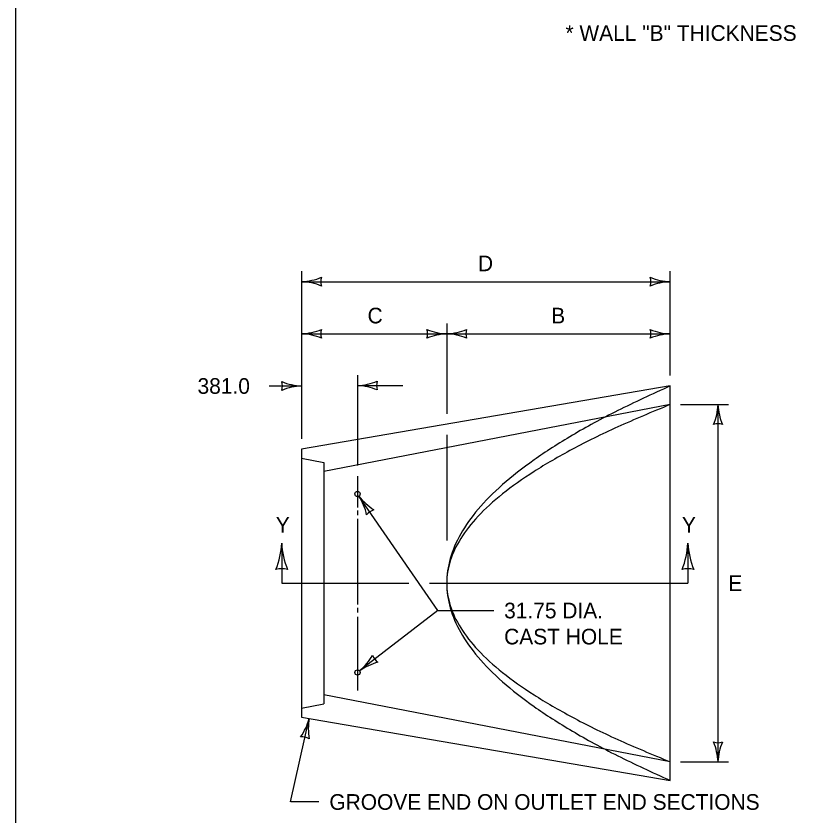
# Model space of a CAD drawing. Extents: x 49991.4 to 50022.1, y 49985 to 50011.4.
# Drawn here: x 49999.384 to 50002.424, y 49989.878 to 49992.942 of the extents above; entities that cross this region are included whole.
import ezdxf

# ---------------------------------------------------------------- set-up
doc = ezdxf.new("R2010")
doc.units = 0
for name, color, linetype in [('Level 1', 7, 'Continuous'), ('Level 2', 7, 'Continuous'), ('Level 3', 7, 'Continuous'), ('Level 4', 7, 'Continuous'), ('Level 5', 7, 'Continuous'), ('Level 6', 7, 'Continuous')]:
    doc.layers.add(name, color=color, linetype=linetype)

msp = doc.modelspace()

# ---------------------------------------------------------------- linework, layer by layer
at = {"layer": 'Level 1'}
for p, q in [((50001.8913, 49991.5236), (50000.4787, 49991.281)), ((50001.8913, 49990.011), (50001.8913, 49991.5236)), ((50000.4787, 49991.281), (50000.4787, 49990.2536)), ((50000.4787, 49990.2536), (50001.8913, 49990.011))]:
    msp.add_line(p, q, dxfattribs=at)
msp.add_lwpolyline([(49999.3835, 49998.9992), (50016.7501, 49998.9992), (50016.7501, 49987.7988), (49999.3835, 49987.7988)], close=True, dxfattribs=at)
for centre in [(50000.6927, 49991.1097), (50000.6927, 49990.4248)]:
    msp.add_circle(centre, 0.0102, dxfattribs=at)
for points in [[(50001.8913, 49991.5236), (50000.179, 49990.7673), (50001.8913, 49990.011)], [(50001.8913, 49991.4522), (50000.179, 49990.7673), (50001.8913, 49990.0823)]]:
    msp.add_open_spline(points, degree=2, dxfattribs=at)
at = {"layer": 'Level 3'}
for p, q in [((50000.4787, 49991.9636), (50000.4787, 49991.321)), ((50001.8913, 49991.5636), (50001.8913, 49991.9636)), ((50000.4787, 49991.9236), (50001.8913, 49991.9236)), ((50001.0352, 49991.7636), (50001.0352, 49991.4166)), ((50000.4787, 49991.7236), (50001.0352, 49991.7236)), ((50001.0352, 49991.7236), (50001.8913, 49991.7236)), ((50000.6927, 49991.5652), (50000.6927, 49991.3207)), ((50000.3537, 49991.5236), (50000.4787, 49991.5236)), ((50000.6927, 49991.5252), (50000.8661, 49991.5252)), ((50001.9313, 49991.4522), (50002.115, 49991.4522)), ((50002.075, 49991.4522), (50002.075, 49990.0823)), ((50001.0352, 49991.3366), (50001.0352, 49991.258)), ((50000.6927, 49991.3207), (50000.6927, 49991.2182)), ((50001.0352, 49991.258), (50001.0352, 49990.9309)), ((50001.0014, 49990.6625), (50000.6985, 49991.1013)), ((50001.0014, 49990.6625), (50000.7008, 49990.431)), ((50001.0014, 49990.6625), (50001.2151, 49990.6625)), ((50000.4364, 49989.9283), (50000.5077, 49990.2486)), ((50001.9313, 49990.0823), (50002.115, 49990.0823)), ((50000.545, 49989.9283), (50000.4377, 49989.9283))]:
    msp.add_line(p, q, dxfattribs=at)
for centre, radius, start, end in [((50000.4672, 49992.1563), 0.233, 272.8273, 292.0772), ((50000.4695, 49991.7015), 0.2223, 67.456, 87.6395), ((50000.6069, 49991.9236), 0.0548, 162.1388, 197.8612), ((50001.9005, 49992.1457), 0.2223, 247.456, 267.6395), ((50001.7631, 49991.9236), 0.0548, 342.1388, 17.8612), ((50001.9028, 49991.6909), 0.233, 92.8273, 112.0772), ((50000.4672, 49991.9563), 0.233, 272.8273, 292.0772), ((50000.6069, 49991.7236), 0.0548, 162.1388, 197.8612), ((50001.0444, 49991.9457), 0.2223, 247.456, 267.6395), ((50000.907, 49991.7236), 0.0548, 342.1388, 17.8612), ((50001.0237, 49991.9563), 0.233, 272.8273, 292.0772), ((50001.1634, 49991.7236), 0.0548, 162.1388, 197.8612), ((50001.9005, 49991.9457), 0.2223, 247.456, 267.6395), ((50001.7631, 49991.7236), 0.0548, 342.1388, 17.8612), ((50000.4695, 49991.5015), 0.2223, 67.456, 87.6395), ((50001.0467, 49991.4909), 0.233, 92.8273, 112.0772), ((50001.026, 49991.5015), 0.2223, 67.456, 87.6395), ((50001.9028, 49991.4909), 0.233, 92.8273, 112.0772), ((50000.4879, 49991.7457), 0.2223, 247.456, 267.6395), ((50000.3505, 49991.5236), 0.0548, 342.1388, 17.8612), ((50000.4902, 49991.2909), 0.233, 92.8273, 112.0772), ((50000.6812, 49991.7579), 0.233, 272.8273, 292.0772), ((50000.6835, 49991.3031), 0.2223, 67.456, 87.6395), ((50000.8209, 49991.5252), 0.0548, 162.1388, 197.8612), ((50001.8529, 49991.4614), 0.2223, 337.456, 357.6395), ((50002.3077, 49991.4637), 0.233, 182.8273, 202.0772), ((50002.075, 49991.324), 0.0548, 72.1388, 107.8612), ((50000.5105, 49990.9827), 0.2223, 12.073, 32.2565), ((50000.8835, 49991.243), 0.233, 217.4443, 236.6942), ((50000.7713, 49990.9958), 0.0548, 106.7558, 142.4782), ((50000.1061, 49990.9332), 0.2964, 337.456, 357.6395), ((50000.7126, 49990.9363), 0.3107, 182.8273, 202.0772), ((50001.6633, 49990.9332), 0.2964, 337.456, 357.6395), ((50002.2698, 49990.9363), 0.3107, 182.8273, 202.0772), ((50000.4023, 49990.75), 0.073, 72.1388, 107.8612), ((50001.9595, 49990.75), 0.073, 72.1388, 107.8612), ((50000.5497, 49990.6084), 0.233, 310.4281, 329.678), ((50000.8024, 49990.5092), 0.0548, 199.7396, 235.462), ((50000.8291, 49990.2494), 0.2223, 105.0568, 125.2403), ((50000.2928, 49990.3058), 0.2223, 324.9059, 345.0894), ((50000.7373, 49990.2093), 0.233, 170.2772, 189.5271), ((50000.4798, 49990.1235), 0.0548, 59.5887, 95.3111), ((50002.075, 49990.2105), 0.0548, 252.1388, 287.8612), ((50001.8423, 49990.0708), 0.233, 2.8273, 22.0772), ((50002.2971, 49990.0731), 0.2223, 157.456, 177.6395)]:
    msp.add_arc(centre, radius, start, end, dxfattribs=at)
at = {"layer": 'Level 4'}
for p, q in [((50001.8913, 49991.4522), (50000.5642, 49991.1953)), ((50000.4787, 49991.2467), (50000.5642, 49991.2296)), ((50000.5642, 49991.2296), (50000.5642, 49990.305)), ((50001.8913, 49990.0823), (50000.5642, 49990.3392)), ((50000.4787, 49990.2878), (50000.5642, 49990.305))]:
    msp.add_line(p, q, dxfattribs=at)
at = {"layer": 'Level 5'}
for p, q in [((50000.6927, 49991.1782), (50000.6927, 49991.058)), ((50000.6927, 49991.0464), (50000.6927, 49991.0281)), ((50000.6927, 49991.0142), (50000.6927, 49990.6861)), ((50000.6927, 49990.6723), (50000.6927, 49990.655)), ((50000.6927, 49990.6377), (50000.6927, 49990.3563))]:
    msp.add_line(p, q, dxfattribs=at)
at = {"layer": 'Level 6'}
for p, q in [((50000.4023, 49990.921), (50000.4023, 49990.7673)), ((50001.9595, 49990.921), (50001.9595, 49990.7673)), ((50000.4023, 49990.7673), (50000.8891, 49990.7673)), ((50000.9691, 49990.7673), (50001.9595, 49990.7673))]:
    msp.add_line(p, q, dxfattribs=at)

# ---------------------------------------------------------------- texts
at = {"layer": 'Level 2'}
for s, p in [('* WALL "B" THICKNESS', (50001.4902, 49992.847)), ('D', (50001.1547, 49991.9636)), ('C', (50000.7314, 49991.7636)), ('B', (50001.4356, 49991.7636)), ('381.0', (50000.0796, 49991.4936)), ('Y', (50000.3795, 49990.961)), ('Y', (50001.9367, 49990.961)), ('E', (50002.115, 49990.7373)), ('31.75 DIA.', (50001.2551, 49990.6325)), ('CAST HOLE', (50001.2551, 49990.5325)), ('GROOVE END ON OUTLET END SECTIONS', (50000.585, 49989.8983))]:
    msp.add_text(s, height=0.06, dxfattribs=at).set_placement(p)

doc.saveas('drawing.dxf')
